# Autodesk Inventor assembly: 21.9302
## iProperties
Created: 2011-01
Part Number: 21.9302
Document SubType Name: Assembly
Designer: Administrator
Vendor: V
Description: LEVER HANDLE NON LOCKING
Author: Administrator
